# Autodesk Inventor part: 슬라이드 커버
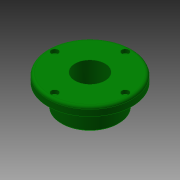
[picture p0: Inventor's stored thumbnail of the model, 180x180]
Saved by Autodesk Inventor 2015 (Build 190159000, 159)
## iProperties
Created: 2015-10
Part Number: 슬라이드 커버
Document SubType Name: Modeling
Designer: mdu
Density: 7.86 g/cm^3
Material: 강철, 연강
Mass: 598.523 g
Surface Area: 229.996 cm^2
Volume: 76.148 cm^3
Appearance: 진녹색
Author: mdu
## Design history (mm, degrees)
sketch "스케치1"
  geometry: C1 r 47.5 at (0, 0); C2 r 32.5 at (0, 0); 1 further point
  constraints: 2 centre point, 2 coincident
  dimensions: "d33" = 95 diameter of C1; "d35" = 65 diameter of C2
extrude "돌출1" new body sketch "스케치1" distance "d0" = 10; taper "d1" = 0 deg
extrude "돌출2" join sketch "스케치1" distance "d2" = 25; taper "d3" = 0 deg
hole "구멍1" diameter "d6" = 36; stored, may be unused: countersink angle "d10" = 90 deg, drill point angle "d12" = 118 deg; dims "d7" = 6, "d8" = 4, "d9" = 2, "d11" = 8, "d41" = 10, "d42" = 10
sketch "스케치2" dims "d36" = 80
  geometry: 4 further points
  constraints: 2 coincident, 2 vertical alignment, 2 other
hole "구멍2" sketch "스케치2" at (0, 40) diameter "d13" = 4.5; stored, may be unused: countersink angle "d17" = 90 deg, drill point angle "d19" = 118 deg; dims "d14" = 6, "d15" = 8, "d16" = 4.4, "d18" = 8
fillet "모깎기1" dims "d23" = 3
chamfer "모따기1" distance "d24" = 1; stored, may be unused: second distance "d25" = 2, angle "d26" = 45 deg
sketch "스케치3"
  geometry: C1 r 26 at (0, 0); C2 r 19 at (0, 0) reference; 1 further point
  constraints: 1 centre point, 1 concentric
  dimensions: "d27" = 52 diameter of C1
extrude "돌출3" cut sketch "스케치3" distance "d28" = 10; taper "d29" = 0 deg
chamfer "모따기2" distance "d30" = 1; stored, may be unused: second distance "d31" = 2, angle "d32" = 45 deg
node "솔리드1"
pattern_circular "원형 패턴1" dims angle "d21" = 360 deg
